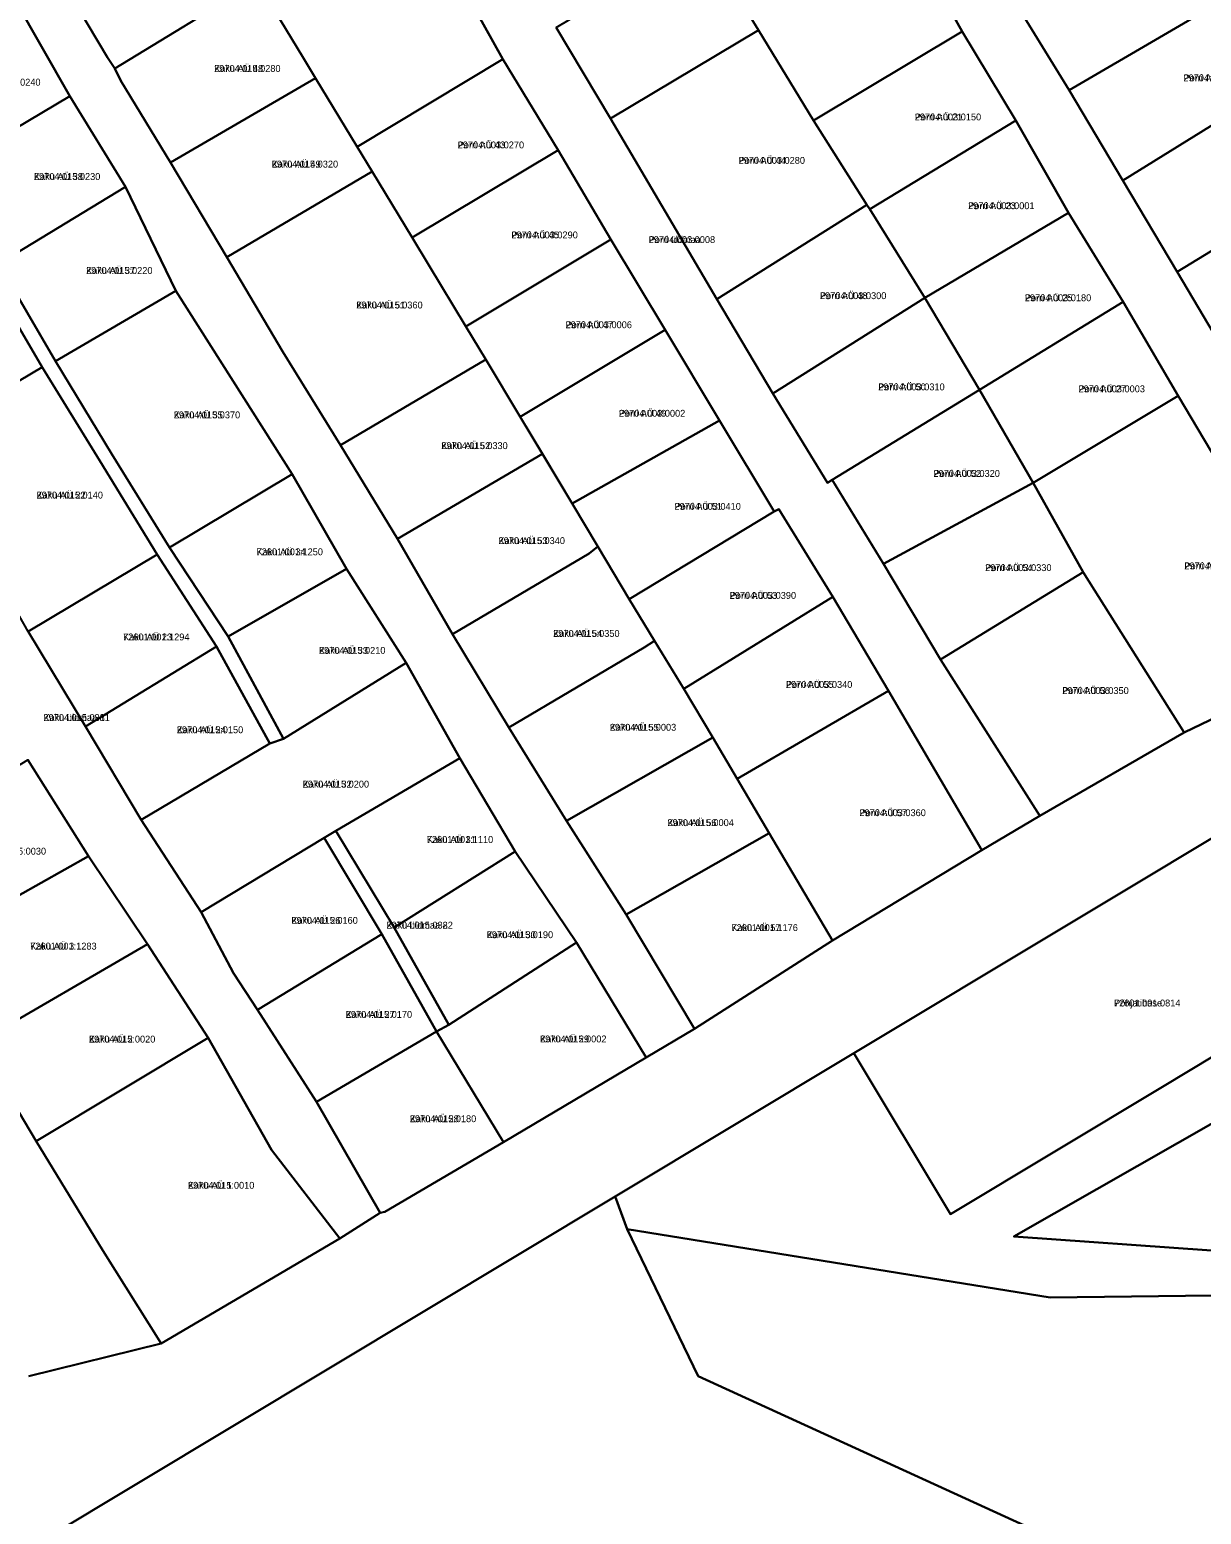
# Model space of a CAD drawing. Extents: x 504287 to 537970, y 6539941 to 6586214.
# Drawn here: x 516278.4 to 516534.2, y 6563396.7 to 6563721 of the extents above; entities that cross this region are included whole.
import ezdxf

# ---------------------------------------------------------------- set-up
doc = ezdxf.new("R2010")
doc.units = 0
for name, color, linetype in [('L_AADRESS', 7, 'Continuous'), ('PIIR', 7, 'Continuous'), ('TUNNUS', 7, 'Continuous')]:
    doc.layers.add(name, color=color, linetype=linetype)

msp = doc.modelspace()

# ---------------------------------------------------------------- linework, layer by layer
at = {"layer": 'PIIR'}
for points in [[(516250.7, 6563862), (516289.63, 6563884.92), (516297.99, 6563871.18), (516322.89, 6563830.27), (516331.63, 6563834.05), (516347.58, 6563843.49), (516367.51, 6563855.22), (516387.24, 6563867.02), (516407.2, 6563878.8), (516439.89, 6563900.56), (516448.37, 6563890.87), (516407.56, 6563866.87), (516420.73, 6563845.22), (516433.95, 6563825.74), (516445.89, 6563806.35), (516458.03, 6563786.3), (516469.7, 6563766.95), (516484.93, 6563741.11), (516493.11, 6563727.7), (516505.34, 6563707.79), (516517.08, 6563688.04), (516528.99, 6563668.1), (516540.37, 6563648.81)], [(516540.67, 6563621.62), (516529.15, 6563640.98), (516517.17, 6563661.5), (516505.2, 6563680.98), (516493.72, 6563701.14), (516481.98, 6563720.54), (516465.46, 6563750.19)], [(516284.51, 6563733.19), (516295.37, 6563714.86), (516296.93, 6563712.51), (516298.27, 6563709.76), (516309.14, 6563691.96), (516321.41, 6563671.28), (516333.64, 6563650.62), (516346.27, 6563630.23), (516358.71, 6563609.77), (516370.68, 6563588.91), (516383.03, 6563568.55), (516395.62, 6563548.17), (516408.61, 6563527.68), (516423.52, 6563502.71), (516413.02, 6563496.45), (516397.76, 6563521.56), (516384.41, 6563541.48), (516372.31, 6563561.82), (516360.59, 6563582.66), (516347.51, 6563603.18), (516335.65, 6563623.9), (516322.8, 6563644.18), (516310.28, 6563663.95), (516299.3, 6563686.62), (516287.14, 6563706.42), (516275.07, 6563727.69)], [(516393.32, 6563721.41), (516405.19, 6563701.54), (516428.46, 6563662.11), (516440.65, 6563641.51), (516452.56, 6563622), (516453.62, 6563622.61), (516464.8, 6563604.25), (516477.28, 6563583.38), (516498.97, 6563549.23), (516486.32, 6563541.77), (516465.94, 6563576.51), (516453.77, 6563597.06), (516441.93, 6563616.25), (516440.91, 6563615.72), (516429.02, 6563635.6), (516417.13, 6563655.4), (516405.29, 6563675.12), (516393.8, 6563694.66), (516381.69, 6563714.5), (516370.46, 6563734.68)], [(516271.52, 6563669.85), (516284, 6563648.59), (516296.27, 6563628.26), (516308.86, 6563607.88), (516321.71, 6563588.43), (516333.76, 6563566.09), (516330.81, 6563565.04), (516319.18, 6563586.25), (516306.16, 6563606.35), (516293.66, 6563626.75), (516281.08, 6563647.25), (516268.98, 6563667.87)], [(516278, 6563589.47), (516290.52, 6563568.76), (516302.68, 6563548.33), (516315.78, 6563528.16), (516322.86, 6563514.9), (516328.09, 6563506.87), (516341.01, 6563486.8), (516354.89, 6563462.52), (516346.09, 6563456.93), (516331.19, 6563476.31), (516317.32, 6563500.77), (516304.08, 6563521.24), (516291.18, 6563540.41), (516277.92, 6563561.48)], [(516278.14, 6563426.87), (516307.05, 6563434), (516346.09, 6563456.93), (516354.89, 6563462.52), (516355.88, 6563462.77), (516381.84, 6563477.94), (516413.02, 6563496.45), (516423.52, 6563502.71), (516453.72, 6563521.97), (516486.32, 6563541.77), (516498.97, 6563549.23), (516530.47, 6563567.46), (516563.56, 6563583.34)], [(516550.89, 6563552.98), (516458.32, 6563497.36), (516406.24, 6563466.08), (516260.12, 6563378.32)], [(516625.46, 6563445.55), (516501.25, 6563444.05), (516408.82, 6563458.96), (516406.24, 6563466.08), (516458.32, 6563497.36), (516479.43, 6563462.22), (516502.57, 6563476.12), (516525.72, 6563490.03), (516548.86, 6563503.93)], [(516266.92, 6563499.65), (516279.74, 6563478.18), (516294.31, 6563454.29), (516307.05, 6563434), (516278.14, 6563426.87)]]:
    msp.add_lwpolyline(points, dxfattribs=at)
for points in [[(516340.78, 6563710.41), (516338.17, 6563714.73), (516328.01, 6563731.51), (516326.26, 6563734.4), (516359.48, 6563754.42), (516381.69, 6563714.5), (516349.89, 6563695.37)], [(516295.37, 6563714.86), (516284.51, 6563733.19), (516315.84, 6563751.99), (516326.26, 6563734.4), (516328.01, 6563731.51), (516296.93, 6563712.51)], [(516437.49, 6563720.84), (516431.29, 6563731.14), (516465.46, 6563750.19), (516481.98, 6563720.54), (516449.55, 6563701.12)], [(516493.11, 6563727.7), (516533.21, 6563751.45), (516545.71, 6563731.34), (516505.34, 6563707.79)], [(516393.32, 6563721.41), (516425.5, 6563740.68), (516431.29, 6563731.14), (516437.49, 6563720.84), (516405.19, 6563701.54)], [(516298.27, 6563709.76), (516296.93, 6563712.51), (516328.01, 6563731.51), (516338.17, 6563714.73), (516340.78, 6563710.41), (516309.14, 6563691.96)], [(516505.34, 6563707.79), (516545.71, 6563731.34), (516556.93, 6563712.69), (516517.08, 6563688.04)], [(516245.73, 6563710.1), (516275.07, 6563727.69), (516287.14, 6563706.42), (516259.16, 6563689.81)], [(516405.19, 6563701.54), (516437.49, 6563720.84), (516449.55, 6563701.12), (516461.16, 6563682.7), (516428.46, 6563662.11)], [(516461.16, 6563682.7), (516449.55, 6563701.12), (516481.98, 6563720.54), (516493.72, 6563701.14), (516461.85, 6563681.75)], [(516353.16, 6563689.96), (516349.89, 6563695.37), (516381.69, 6563714.5), (516393.8, 6563694.66), (516361.87, 6563675.59)], [(516309.14, 6563691.96), (516340.78, 6563710.41), (516349.89, 6563695.37), (516353.16, 6563689.96), (516321.41, 6563671.28)], [(516517.08, 6563688.04), (516556.93, 6563712.69), (516569.06, 6563692.51), (516528.99, 6563668.1)], [(516259.16, 6563689.81), (516287.14, 6563706.42), (516299.3, 6563686.62), (516271.52, 6563669.85)], [(516493.72, 6563701.14), (516505.2, 6563680.98), (516473.87, 6563662.38), (516461.85, 6563681.75)], [(516365.53, 6563669.53), (516361.87, 6563675.59), (516393.8, 6563694.66), (516405.29, 6563675.12), (516373.63, 6563656.11)], [(516528.99, 6563668.1), (516569.06, 6563692.51), (516580.96, 6563672.68), (516540.37, 6563648.81)], [(516241.17, 6563651.02), (516228.99, 6563671.89), (516256.42, 6563688.48), (516268.98, 6563667.87), (516281.08, 6563647.25), (516253.55, 6563630.97)], [(516333.64, 6563650.62), (516321.41, 6563671.28), (516353.16, 6563689.96), (516361.87, 6563675.59), (516365.53, 6563669.53), (516373.63, 6563656.11), (516377.94, 6563648.92), (516346.27, 6563630.23)], [(516271.52, 6563669.85), (516299.3, 6563686.62), (516310.28, 6563663.95), (516284, 6563648.59)], [(516428.46, 6563662.11), (516461.16, 6563682.7), (516461.85, 6563681.75), (516473.87, 6563662.38), (516440.65, 6563641.51)], [(516473.87, 6563662.38), (516505.2, 6563680.98), (516517.17, 6563661.5), (516485.82, 6563642.31)], [(516373.63, 6563656.11), (516405.29, 6563675.12), (516417.13, 6563655.4), (516385.47, 6563636.39), (516377.94, 6563648.92)], [(516296.27, 6563628.26), (516284, 6563648.59), (516310.28, 6563663.95), (516322.8, 6563644.18), (516335.65, 6563623.9), (516308.86, 6563607.88)], [(516452.56, 6563622), (516440.65, 6563641.51), (516473.87, 6563662.38), (516485.82, 6563642.31), (516453.62, 6563622.61)], [(516485.82, 6563642.31), (516517.17, 6563661.5), (516529.15, 6563640.98), (516497.49, 6563622.01)], [(516417.13, 6563655.4), (516429.02, 6563635.6), (516396.84, 6563617.45), (516385.47, 6563636.39)], [(516346.27, 6563630.23), (516377.94, 6563648.92), (516385.47, 6563636.39), (516390.33, 6563628.29), (516358.71, 6563609.77)], [(516266.25, 6563610.24), (516253.55, 6563630.97), (516281.08, 6563647.25), (516293.66, 6563626.75), (516306.16, 6563606.35), (516278, 6563589.47)], [(516453.62, 6563622.61), (516485.82, 6563642.31), (516497.49, 6563622.01), (516464.8, 6563604.25)], [(516497.49, 6563622.01), (516529.15, 6563640.98), (516540.67, 6563621.62), (516563.56, 6563583.34), (516530.47, 6563567.46), (516508.46, 6563602.44)], [(516402.42, 6563608.1), (516396.84, 6563617.45), (516429.02, 6563635.6), (516440.91, 6563615.72), (516409.3, 6563596.58)], [(516358.71, 6563609.77), (516390.33, 6563628.29), (516396.84, 6563617.45), (516402.42, 6563608.1), (516400.52, 6563606.52), (516370.68, 6563588.91)], [(516335.65, 6563623.9), (516347.51, 6563603.18), (516321.71, 6563588.43), (516308.86, 6563607.88)], [(516464.8, 6563604.25), (516497.49, 6563622.01), (516508.46, 6563602.44), (516477.28, 6563583.38)], [(516414.84, 6563587.48), (516409.3, 6563596.58), (516440.91, 6563615.72), (516441.93, 6563616.25), (516453.77, 6563597.06), (516421.21, 6563577.01)], [(516370.68, 6563588.91), (516400.52, 6563606.52), (516402.42, 6563608.1), (516409.3, 6563596.58), (516414.84, 6563587.48), (516412.57, 6563586), (516383.03, 6563568.55)], [(516306.16, 6563606.35), (516319.18, 6563586.25), (516290.52, 6563568.76), (516278, 6563589.47)], [(516321.71, 6563588.43), (516347.51, 6563603.18), (516360.59, 6563582.66), (516333.76, 6563566.09)], [(516477.28, 6563583.38), (516508.46, 6563602.44), (516530.47, 6563567.46), (516498.97, 6563549.23)], [(516427.52, 6563566.32), (516421.21, 6563577.01), (516453.77, 6563597.06), (516465.94, 6563576.51), (516432.83, 6563557.31)], [(516414.84, 6563587.48), (516421.21, 6563577.01), (516427.52, 6563566.32), (516395.62, 6563548.17), (516383.03, 6563568.55), (516412.57, 6563586)], [(516290.52, 6563568.76), (516319.18, 6563586.25), (516330.81, 6563565.04), (516302.68, 6563548.33)], [(516302.68, 6563548.33), (516330.81, 6563565.04), (516333.76, 6563566.09), (516360.59, 6563582.66), (516372.31, 6563561.82), (516345.24, 6563545.99), (516342.67, 6563544.43), (516315.78, 6563528.16)], [(516432.83, 6563557.31), (516465.94, 6563576.51), (516486.32, 6563541.77), (516453.72, 6563521.97), (516439.84, 6563545.42)], [(516395.62, 6563548.17), (516427.52, 6563566.32), (516432.83, 6563557.31), (516439.84, 6563545.42), (516408.61, 6563527.68)], [(516242.32, 6563539.8), (516277.92, 6563561.48), (516291.18, 6563540.41), (516254.94, 6563520.03)], [(516372.31, 6563561.82), (516384.41, 6563541.48), (516357.93, 6563524.83), (516345.24, 6563545.99)], [(516458.32, 6563497.36), (516550.89, 6563552.98), (516572.01, 6563517.83), (516548.86, 6563503.93), (516525.72, 6563490.03), (516502.57, 6563476.12), (516479.43, 6563462.22)], [(516357.93, 6563524.83), (516369.86, 6563503.56), (516367.19, 6563502.11), (516355.26, 6563523.39), (516342.67, 6563544.43), (516345.24, 6563545.99)], [(516408.61, 6563527.68), (516439.84, 6563545.42), (516453.72, 6563521.97), (516423.52, 6563502.71)], [(516322.86, 6563514.9), (516315.78, 6563528.16), (516342.67, 6563544.43), (516355.26, 6563523.39), (516328.09, 6563506.87)], [(516266.92, 6563499.65), (516262.63, 6563507), (516258.46, 6563513.85), (516254.94, 6563520.03), (516291.18, 6563540.41), (516304.08, 6563521.24)], [(516357.93, 6563524.83), (516384.41, 6563541.48), (516397.76, 6563521.56), (516369.86, 6563503.56)], [(516328.09, 6563506.87), (516355.26, 6563523.39), (516367.19, 6563502.11), (516341.01, 6563486.8)], [(516266.92, 6563499.65), (516304.08, 6563521.24), (516317.32, 6563500.77), (516279.74, 6563478.18)], [(516367.19, 6563502.11), (516369.86, 6563503.56), (516397.76, 6563521.56), (516413.02, 6563496.45), (516381.84, 6563477.94)], [(516617.86, 6563457.38), (516597.41, 6563489.08), (516585.53, 6563509.93), (516555.99, 6563493.09), (516493.29, 6563457.33), (516536.45, 6563454.32)], [(516493.29, 6563457.33), (516555.99, 6563493.09), (516585.53, 6563509.93), (516597.41, 6563489.08), (516567.88, 6563472.24), (516536.45, 6563454.32)], [(516294.31, 6563454.29), (516279.74, 6563478.18), (516317.32, 6563500.77), (516331.19, 6563476.31), (516346.09, 6563456.93), (516307.05, 6563434)], [(516354.89, 6563462.52), (516341.01, 6563486.8), (516367.19, 6563502.11), (516381.84, 6563477.94), (516355.88, 6563462.77)], [(516695.62, 6563139.08), (516624.31, 6563237.9), (516346.02, 6563331.56), (516332.21, 6563355.36), (516260.12, 6563378.32), (516406.24, 6563466.08), (516408.82, 6563458.96), (516424.36, 6563426.81), (516715.46, 6563293.57), (516771.07, 6563193.22)], [(516501.25, 6563444.05), (516625.46, 6563445.55), (516633.11, 6563437.06), (516884.06, 6563418.3), (516888.62, 6563294.88), (516865.54, 6563151.5), (516892.22, 6563104.11), (516896.52, 6563093.71), (516896.31, 6563070.84), (516900.68, 6563071.4), (516864.48, 6563024.66), (516715.46, 6563293.57), (516424.36, 6563426.81), (516408.82, 6563458.96)]]:
    msp.add_lwpolyline(points, close=True, dxfattribs=at)

# ---------------------------------------------------------------- texts
at = {"layer": 'L_AADRESS'}
for s, p in [('Kaku AÜ 48', (516318.64, 6563711.74)), ('Porri AÜ 22', (516530.34, 6563709.69)), ('Porri AÜ 21', (516471.65, 6563701.15)), ('Porri AÜ 43', (516371.83, 6563695.04)), ('Kaku AÜ 49', (516331.21, 6563690.85)), ('Porri AÜ 44', (516433.17, 6563691.67)), ('Kaku AÜ 38', (516279.28, 6563688.14)), ('Porri AÜ 23', (516483.31, 6563681.76)), ('Porri AÜ 45', (516383.56, 6563675.38)), ('Porri üldmaa', (516413.55, 6563674.36)), ('Kaku AÜ 37', (516290.67, 6563667.61)), ('Kaku AÜ 51', (516349.67, 6563660.07)), ('Porri AÜ 48', (516450.95, 6563662.11)), ('Porri AÜ 25', (516495.69, 6563661.65)), ('Porri AÜ 47', (516395.38, 6563655.76)), ('Porri AÜ 50', (516463.68, 6563642.19)), ('Porri AÜ 27', (516507.42, 6563641.76)), ('Kaku AÜ 35', (516309.82, 6563636.07)), ('Porri AÜ 49', (516407.03, 6563636.42)), ('Kaku AÜ 52', (516368.25, 6563629.35)), ('Porri AÜ 52', (516475.74, 6563623.28)), ('Kaku AÜ 22', (516279.85, 6563618.55)), ('Porri AÜ 51', (516419.17, 6563616.09)), ('Kaku AÜ 53', (516380.75, 6563608.6)), ('Kaku AÜ 34', (516327.9, 6563606.16)), ('Porri AÜ 54', (516487.02, 6563602.7)), ('Porri AÜ 29', (516530.53, 6563603.08)), ('Porri AÜ 53', (516431.23, 6563596.63)), ('Kaku AÜ 23', (516298.75, 6563587.56)), ('Kaku AÜ 54', (516392.68, 6563588.33)), ('Kaku AÜ 33', (516341.54, 6563584.63)), ('Porri AÜ 55', (516443.52, 6563577.18)), ('Porri AÜ 56', (516503.88, 6563575.85)), ('Kaku üldmaa 1', (516281.37, 6563569.95)), ('Kaku AÜ 24', (516310.49, 6563567.29)), ('Kaku AÜ 55', (516405.05, 6563567.83)), ('Kaku AÜ 32', (516337.97, 6563555.41)), ('Kaku AÜ 56', (516417.64, 6563547)), ('Porri AÜ 57', (516459.57, 6563549.17)), ('Kaku AÜ 31', (516365.08, 6563543.32)), ('Kaku AÜ 26', (516335.51, 6563525.65)), ('Kaku üldmaa 2', (516356.27, 6563524.6)), ('Kaku AÜ 57', (516431.62, 6563524.07)), ('Kaku AÜ 30', (516378.17, 6563522.52)), ('Kaku AÜ 3', (516278.47, 6563520.03)), ('Kaku AÜ 27', (516347.37, 6563505.1)), ('Põhjatihase', (516515.17, 6563507.6)), ('Kaku AÜ 2', (516291.29, 6563499.71)), ('Kaku AÜ 29', (516389.82, 6563499.75)), ('Kaku AÜ 28', (516361.38, 6563482.32)), ('Kaku AÜ 1', (516312.92, 6563467.78))]:
    msp.add_text(s, height=1.5, dxfattribs=at).set_placement(p)
at = {"layer": 'TUNNUS'}
for s, p in [('29704:015:0280', (516318.64, 6563711.74)), ('29704:003:0160', (516530.34, 6563709.69)), ('29704:015:0240', (516266.22, 6563708.75)), ('29704:003:0150', (516471.65, 6563701.15)), ('29704:003:0270', (516371.83, 6563695.04)), ('29704:015:0320', (516331.21, 6563690.85)), ('29704:003:0280', (516433.17, 6563691.67)), ('29704:015:0230', (516279.28, 6563688.14)), ('29704:003:0001', (516483.31, 6563681.76)), ('29704:003:0290', (516383.56, 6563675.38)), ('29704:003:0008', (516413.55, 6563674.36)), ('29704:015:0220', (516290.67, 6563667.61)), ('29704:003:0300', (516450.95, 6563662.11)), ('29704:003:0180', (516495.69, 6563661.65)), ('29704:015:0360', (516349.67, 6563660.07)), ('29704:003:0006', (516395.38, 6563655.76)), ('29704:003:0310', (516463.68, 6563642.19)), ('29704:003:0003', (516507.42, 6563641.76)), ('29704:015:0370', (516309.82, 6563636.07)), ('29704:003:0002', (516407.03, 6563636.42)), ('29704:015:0330', (516368.25, 6563629.35)), ('29704:003:0320', (516475.74, 6563623.28)), ('29704:015:0140', (516279.85, 6563618.55)), ('29704:003:0410', (516419.17, 6563616.09)), ('29704:015:0340', (516380.75, 6563608.6)), ('72601:001:1250', (516327.9, 6563606.16)), ('29704:003:0330', (516487.02, 6563602.7)), ('29704:003:0200', (516530.53, 6563603.08)), ('29704:003:0390', (516431.23, 6563596.63)), ('72601:001:1294', (516298.75, 6563587.56)), ('29704:015:0350', (516392.68, 6563588.33)), ('29704:015:0210', (516341.54, 6563584.63)), ('29704:003:0340', (516443.52, 6563577.18)), ('29704:003:0350', (516503.88, 6563575.85)), ('29704:015:0381', (516281.37, 6563569.95)), ('29704:015:0150', (516310.49, 6563567.29)), ('29704:015:0003', (516405.05, 6563567.83)), ('29704:015:0200', (516337.97, 6563555.41)), ('29704:015:0004', (516417.64, 6563547)), ('29704:003:0360', (516459.57, 6563549.17)), ('29704:015:0030', (516267.43, 6563540.76)), ('72601:001:1110', (516365.08, 6563543.32)), ('29704:015:0160', (516335.51, 6563525.65)), ('29704:015:0382', (516356.27, 6563524.6)), ('72601:001:1176', (516431.62, 6563524.07)), ('29704:015:0190', (516378.17, 6563522.52)), ('72601:001:1283', (516278.47, 6563520.03)), ('29704:015:0170', (516347.37, 6563505.1)), ('72601:001:0814', (516515.17, 6563507.6)), ('29704:015:0020', (516291.29, 6563499.71)), ('29704:015:0002', (516389.82, 6563499.75)), ('29704:015:0180', (516361.38, 6563482.32)), ('29704:015:0010', (516312.92, 6563467.78))]:
    msp.add_text(s, height=1.5, dxfattribs=at).set_placement(p)

doc.saveas('drawing.dxf')
